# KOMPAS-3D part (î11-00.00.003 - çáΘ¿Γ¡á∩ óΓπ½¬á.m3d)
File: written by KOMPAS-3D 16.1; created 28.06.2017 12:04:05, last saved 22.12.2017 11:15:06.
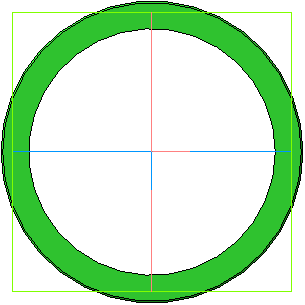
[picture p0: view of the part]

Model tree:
1. Эскиз:1
2. Операция выдавливания:1
     Расстояние 1 = 12
3. Эскиз:2
4. Вырезать элемент вращения:1
     Угол 1 = 360
5. Скругление:1
     Радиус = 0.4
6. Скругление:2
     Радиус = 0.2
7. Фаска:1
     Угол = 45; Длина 1 = 0.3; Длина 2 = 0.3

Expressions: 44+0.1
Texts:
  Фторопласт-4  ГОСТ 10007-80 Е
